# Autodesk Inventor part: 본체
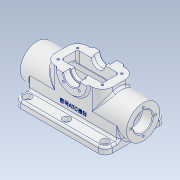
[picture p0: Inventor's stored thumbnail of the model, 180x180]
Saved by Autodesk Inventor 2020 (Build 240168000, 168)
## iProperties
Created: 2024-06
Part Number: 본체
Material: 알루미늄 6061
Document SubType Name: Modeling
Designer: oem
Density: 2.7 g/cm^3
Appearance: 알루미늄 - 평지
Mass: 550.306 g
Surface Area: 613.672 cm^2
Volume: 203.817 cm^3
Author: oem
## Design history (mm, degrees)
sketch "스케치3"
  geometry: L1 (0, 0)-(154, 0); L2 (0, 24)-(154, 24); L3 (0, 0)-(0, 24); L4 (154, 24)-(154, 0)
  constraints: 8 end point, 2 horizontal, 1 vertical
  dimensions: "d6" = 48 diameter of L2 L1; "d7" = 154 distance of L2.start L2.end; "d8" = 154 distance of L1.start L1.end
revolve "회전1" sketch "스케치3" stored, may be unused: angle "d9" = 90 deg
node "작업 평면1"
sketch "스케치4"
  geometry: L1 (-11, -44)-(-143, -44); L2 (-143, -44)-(-143, 44); L3 (-143, 44)-(-11, 44); L4 (-11, 44)-(-11, -44); L5 (0, -24)-(-154, -24) reference; 6 further points
  constraints: 8 end point, 3 midpoint, 2 parallel, 1 horizontal, 1 horizontal alignment, 1 perpendicular, 1 vertical alignment
  dimensions: "d11" = 132 distance of L1.start L1.end; "d12" = 88 distance of L3.end L1.start
extrude "돌출2" join sketch "스케치4" distance "d13" = 10; taper "d14" = 0 deg
node "작업 평면2"
sketch "스케치5"
  geometry: L1 (-35, -24)-(-119, -24); L2 (-119, -24)-(-119, 24); L3 (-119, 24)-(-35, 24); L4 (-35, 24)-(-35, -24); L5 (0, -24)-(-154, -24) reference; 6 further points
  constraints: 8 end point, 3 midpoint, 2 parallel, 1 coincident, 1 horizontal, 1 horizontal alignment, 1 perpendicular
  dimensions: "d16" = 84 distance of L1.start L1.end; "d17" = 48 distance of L3.end L1.start
extrude "돌출3" join sketch "스케치5" stored distance "d18" = 20; taper "d19" = 0 deg
sketch "스케치7"
  geometry: L1 (11, -15.875)-(11, -44) reference; L2 (143, -44)-(143, -15.875) reference; L3 (0, 24)-(154, 24) reference; L4 (0, -24)-(154, -24) reference; L5 (11, 44)-(11, -44) reference; L6 (143, -44)-(143, 44) reference; L7 (11, 24)-(143, 24); L8 (143, 24)-(143, -24); L9 (143, -24)-(11, -24); L10 (11, -24)-(11, 24); 4 further points
  constraints: 8 end point, 4 point on line, 2 parallel, 1 horizontal, 1 perpendicular
extrude "돌출5" join sketch "스케치7" stored distance "d28" = 10; taper "d29" = 0 deg
sketch "스케치9"
  geometry: L1 (119, 31)-(35, 31) reference; L2 (99, 31)-(55, 31); A1 r 22 centre (77, 31) between (99, 31) and (55, 31); 2 further points
  constraints: 2 end point, 2 point on circle, 2 point on line, 1 centre point, 1 coincident, 1 midpoint
  dimensions: "d33" = 44 diameter of A1
extrude "돌출7" join sketch "스케치9" stored distance "d34" = 54; taper "d35" = 0 deg
sketch "스케치10"
  geometry: L1 (55, 27)-(99, 27) reference; L2 (47, 12)-(107, 12); L3 (107, 12)-(107, -12); L4 (107, -12)-(47, -12); L5 (47, -12)-(47, 12); 4 further points
  constraints: 8 end point, 3 midpoint, 2 parallel, 1 horizontal, 1 horizontal alignment, 1 perpendicular, 1 vertical alignment
  dimensions: "d36" = 60 distance of L2.start L2.end; "d37" = 24 distance of L4.end L2.start
extrude "돌출8" cut sketch "스케치10" extent not by distance; stored distance "d38" = 0; taper "d39" = 0 deg
node "작업 평면3"
sketch "스케치11"
  geometry: L1 (9, -27)-(31, -27) reference; L2 (19, -27)-(19, -17); L3 (19, -17)-(21, -17); L4 (21, -17)-(21, 17); L5 (21, 17)-(19, 17); L6 (19, 17)-(19, 27); L7 (31, 27)-(9, 27) reference; L8 (31, -27)-(31, -24) reference; L9 (31, -27)-(31, 27); 2 further points
  constraints: 12 end point, 4 point on line, 3 perpendicular, 2 vertical
  dimensions: "d41" = 10 distance of L2.start L2.end; "d42" = 10 distance of L5.end L6.end; "d43" = 24 diameter of L6 L9; "d44" = 20 diameter of L4 L9
revolve "회전3" sketch "스케치11" stored, may be unused: angle "d45" = 90 deg
sketch "스케치12"
  geometry: L1 (0, -24)-(0, 24) reference; L2 (0, 14)-(15, 14); L3 (15, 14)-(15, 11); L4 (139, 11)-(139, 14); L5 (139, 14)-(154, 14); L6 (154, -24)-(154, 24) reference; L7 (0, 0)-(154, 0); L8 (15, 11)-(17, 11); L9 (17, 11)-(17, 18); L10 (17, 18)-(137, 18); L11 (137, 18)-(137, 11); L12 (137, 11)-(139, 11); A1 r 10 centre (77, 31) between (67, 31) and (87, 31) reference; 2 further points
  constraints: 20 end point, 5 perpendicular, 5 point on line, 2 horizontal, 2 midpoint, 1 point on circle, 1 vertical alignment
  dimensions: "d46" = 15 distance of L2.start L2.end; "d47" = 15 distance of L4.end L5.end; "d48" = 28 diameter of L2 L7; "d59" = 36 diameter of L10 L7; "d60" = 120 distance of L9.end L10.end; "d61" = 22 diameter of L12 L7
revolve "회전4" sketch "스케치12" stored, may be unused: angle "d50" = 90 deg
sketch "스케치13"
  geometry: L1 (107, 12)-(107, -12) reference; L2 (107, -12)-(47, -12) reference; L3 (47, -12)-(47, 12) reference; L4 (47, 12)-(107, 12) reference; L5 (11, -44)-(11, 44) reference; L6 (143, 44)-(143, -44) reference; L7 (17, 18)-(137, 18); L8 (137, 18)-(137, -18); L9 (137, -18)-(17, -18); L10 (17, -18)-(17, 18); L11 (143, 24)-(11, 24) reference; L12 (11, -24)-(143, -24) reference; 1 further point
  constraints: 8 end point, 2 parallel, 1 horizontal, 1 perpendicular
  dimensions: "d52" = 6 distance between parallel lines of L5 L10; "d54" = 6 distance between parallel lines of L6 L8; "d55" = 6 distance between parallel lines of L9 L12; "d56" = 6 distance between parallel lines of L11 L7
extrude "돌출9" cut sketch "스케치13" distance "d57" = 28; taper "d58" = 0 deg
fillet "모깎기1" dims "d62" = 10
sketch "스케치14"
  geometry: L1 (133, 44)-(21, 44) reference; A1 r 10 centre (21, 34) between (21, 44) and (11, 34) reference; A2 r 10 centre (133, 34) between (143, 34) and (133, 44) reference; A3 r 10 centre (21, -34) between (11, -34) and (21, -44) reference; A4 r 10 centre (133, -34) between (133, -44) and (143, -34) reference; 8 further points
  constraints: 4 coincident, 2 horizontal alignment, 2 vertical alignment, 1 midpoint
hole "구멍1" sketch "스케치14" at (133, 34), (77, 34), (21, 34), (21, -34), (77, -34), (133, -34) diameter "d63" = 6.6; stored, may be unused: countersink angle "d67" = 90 deg, drill point angle "d69" = 118 deg; dims "d64" = 11, "d65" = 11, "d66" = 6.6, "d68" = 8
sketch "스케치15"
  geometry: C1 r 14 at (0, 0) reference; C2 r 24 at (0, 0) reference; A1 r 18 centre (0, 0) between (0, 18) and (0, -18); 2 further points
  constraints: 3 point on circle, 2 vertical alignment, 1 centre point, 1 coincident, 1 horizontal alignment
  dimensions: "d70" = 36 diameter of A1
hole "구멍2" sketch "스케치15" at (0, 18), (0, -18), (18, 0), (-18, 0) diameter "d71" = 3.242; stored, may be unused: countersink angle "d75" = 82 deg, drill point angle "d77" = 118 deg; dims "d72" = 8, "d73" = 3.023, "d74" = 6.6, "d76" = 10
sketch "스케치16"
  geometry: C1 r 24 at (0, 0) reference; C2 r 1.621 at (0, -18) reference; A1 r 18 centre (0, 0) between (0, 18) and (18, 0); A2 r 18 centre (0, 0) between (18, 0) and (-18, 0) reference; 1 further point
  constraints: 2 coincident, 2 point on circle, 1 centre point
hole "구멍3" sketch "스케치16" at (0, 18), (18, 0), (0, -18), (-18, 0) diameter "d79" = 3.242; stored, may be unused: countersink angle "d83" = 82 deg, drill point angle "d85" = 118 deg; dims "d80" = 8, "d81" = 3.023, "d82" = 6.6, "d84" = 10
fillet "모깎기2" dims "d86" = 15
sketch "스케치17"
  geometry: L1 (45, -14)-(109, -14); L2 (109, -14)-(109, 14); L3 (109, 14)-(45, 14); L4 (45, 14)-(45, -14); L5 (65, 27)-(89, 27) reference; A1 r 15 centre (50, -9) between (35, -9) and (50, -24) reference; A2 r 15 centre (50, 9) between (50, 24) and (35, 9) reference; 8 further points
  constraints: 8 end point, 4 coincident, 3 midpoint, 2 parallel, 1 horizontal, 1 horizontal alignment, 1 perpendicular, 1 vertical alignment
  dimensions: "d87" = 64 distance of L2.end L3.end; "d88" = 28 distance of L3.end L1.start
fillet "모깎기3" dims "d89" = 3
hole "구멍4" sketch "스케치17" diameter "d90" = 3.242; stored, may be unused: countersink angle "d94" = 82 deg, drill point angle "d96" = 118 deg; dims "d91" = 8, "d92" = 3.023, "d93" = 6.6, "d95" = 10
sketch "스케치18"
  geometry: L1 (-77, 31)-(-77, 15); L2 (-77, 31)-(-88.314, 19.686); L3 (-77, 31)-(-65.686, 19.686); A1 r 22 centre (-77, 31) between (-99, 31) and (-55, 31) reference; A2 r 16 centre (-77, 31) between (-88.314, 19.686) and (-65.686, 19.686); 1 further point
  constraints: 6 end point, 3 point on circle, 1 centre point, 1 coincident, 1 vertical
  dimensions: "d97" = 32 diameter of A2; "d98" = 45 deg angle of L2 L1; "d99" = 45 deg angle of L3 L1
hole "구멍5" sketch "스케치18" at (-88.314, 19.686), (-65.686, 19.686) diameter "d100" = 3.242; stored, may be unused: countersink angle "d104" = 82 deg, drill point angle "d106" = 118 deg; dims "d101" = 8, "d102" = 3.023, "d103" = 6.6, "d105" = 10
sketch "스케치19"
  geometry: L1 (65.686, 19.686)-(77, 31); L2 (77, 31)-(88.314, 19.686); L3 (77, 31)-(77, 15); A1 r 22 centre (77, 31) between (55, 31) and (99, 31) reference; A2 r 16 centre (77, 31) between (65.686, 19.686) and (88.314, 19.686); 1 further point
  constraints: 6 end point, 3 point on circle, 1 centre point, 1 coincident, 1 vertical
  dimensions: "d107" = 32 diameter of A2; "d108" = 45 deg angle of L2 L3; "d109" = 45 deg angle of L1 L3
hole "구멍6" sketch "스케치19" at (65.686, 19.686), (88.314, 19.686) diameter "d110" = 3.242; stored, may be unused: countersink angle "d114" = 82 deg, drill point angle "d116" = 118 deg; dims "d111" = 8, "d112" = 3.023, "d113" = 6.6, "d115" = 10
fillet "모깎기4" dims "d117" = 0.3
fillet "모깎기5" dims "d118" = 3
fillet "모깎기6" dims "d119" = 3
fillet "모깎기7" dims "d120" = 3
fillet "모깎기8" dims "d121" = 3
chamfer "모따기1" distance "d122" = 1; stored, may be unused: second distance "d123" = 2, angle "d124" = 45 deg
chamfer "모따기2" distance "d125" = 1; stored, may be unused: second distance "d126" = 2, angle "d127" = 45 deg
fillet "모깎기9" dims "d128" = 3
fillet "모깎기10" dims "d129" = 3
sketch "스케치20"
  geometry: L1 (7, -13)-(119, -13) reference; A1 r 25 centre (63, 46) between (38, 46) and (88, 46) reference; 2 further points
  constraints: 1 vertical alignment, 1 other
  dimensions: "d130" = 20 distance from line of L1 point (63, 7)
feature "엠보싱1" sketch "스케치20" dims "d16" = 84, "d17" = 48, "d131" = 0.5, "d132" = 0
node "솔리드2"
feature "A9D066F2-1C7D-4E18-AEED-F7BC21143FA4" dims "d63" = 6.6, "d64" = 11, "d65" = 11, "d66" = 6.6, "d67" = 90 deg, "d68" = 8, "d69" = 118 deg
other parameters: "d10" = -28, "d15" = 31, "d40" = 77
